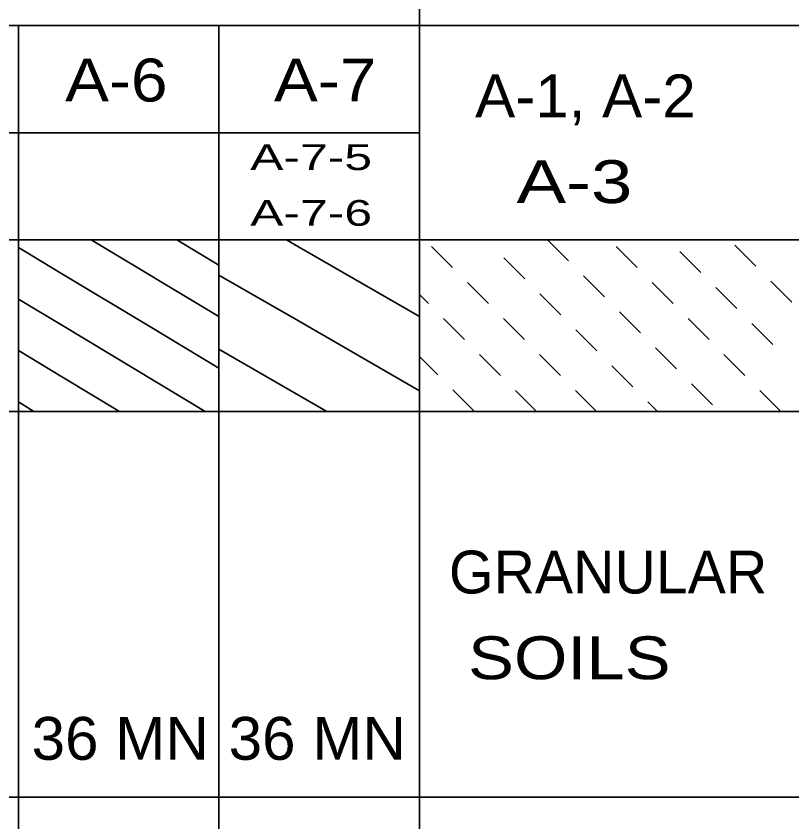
# Model space of a CAD drawing. Extents: x 2137492.6 to 2137529.1, y 2137475.8 to 2137563.
# Drawn here: x 2137498.33 to 2137500.14, y 2137553.765 to 2137555.645 of the extents above; entities that cross this region are included whole.
import ezdxf
from ezdxf.enums import TextEntityAlignment as Align

# ---------------------------------------------------------------- set-up
doc = ezdxf.new("R2010")
doc.units = 0
doc.header["$LTSCALE"] = 0.04
doc.layers.add('1', color=7, linetype='Continuous', lineweight=35)

msp = doc.modelspace()

# ---------------------------------------------------------------- linework, layer by layer
at = {"layer": '1'}
for p, q in [((2137499.271, 2137556.123), (2137499.271, 2137551.631)), ((2137499.271, 2137556.123), (2137499.271, 2137555.098)), ((2137493.171, 2137555.623), (2137501.871, 2137555.623)), ((2137498.335, 2137554.186), (2137498.335, 2137555.623)), ((2137498.803, 2137552.923), (2137498.803, 2137555.623)), ((2137494.121, 2137555.373), (2137499.271, 2137555.373)), ((2137493.171, 2137555.123), (2137501.871, 2137555.123)), ((2137498.505, 2137555.123), (2137498.803, 2137554.944)), ((2137498.705, 2137555.123), (2137498.803, 2137555.064)), ((2137498.989, 2137555.107), (2137498.961, 2137555.123)), ((2137499.57, 2137555.123), (2137499.619, 2137555.074)), ((2137500.056, 2137555.062), (2137500.007, 2137555.111)), ((2137498.335, 2137555.105), (2137498.438, 2137555.043)), ((2137499.271, 2137554.944), (2137498.989, 2137555.107)), ((2137499.271, 2137553.823), (2137499.271, 2137555.093)), ((2137499.348, 2137555.059), (2137499.299, 2137555.108)), ((2137499.779, 2137555.059), (2137499.73, 2137555.108)), ((2137499.879, 2137555.096), (2137499.928, 2137555.047)), ((2137499.517, 2137555.032), (2137499.468, 2137555.081)), ((2137498.438, 2137555.043), (2137498.638, 2137554.923)), ((2137498.989, 2137554.934), (2137498.803, 2137555.041)), ((2137499.654, 2137555.039), (2137499.703, 2137554.99)), ((2137499.432, 2137554.975), (2137499.383, 2137555.024)), ((2137499.863, 2137554.975), (2137499.814, 2137555.024)), ((2137500.14, 2137554.978), (2137500.091, 2137555.027)), ((2137499.601, 2137554.948), (2137499.552, 2137554.997)), ((2137499.963, 2137555.012), (2137500.012, 2137554.963)), ((2137498.335, 2137554.985), (2137498.438, 2137554.923)), ((2137499.292, 2137554.975), (2137499.271, 2137554.996)), ((2137499.738, 2137554.955), (2137499.787, 2137554.906)), ((2137498.438, 2137554.923), (2137498.771, 2137554.723)), ((2137498.638, 2137554.923), (2137498.803, 2137554.824)), ((2137499.271, 2137554.771), (2137498.989, 2137554.934)), ((2137499.376, 2137554.891), (2137499.327, 2137554.94)), ((2137499.516, 2137554.891), (2137499.467, 2137554.94)), ((2137499.947, 2137554.891), (2137499.898, 2137554.94)), ((2137500.047, 2137554.928), (2137500.096, 2137554.879)), ((2137499.636, 2137554.913), (2137499.685, 2137554.864)), ((2137498.335, 2137554.865), (2137498.438, 2137554.803)), ((2137498.989, 2137554.761), (2137498.803, 2137554.868)), ((2137499.822, 2137554.871), (2137499.871, 2137554.822)), ((2137499.314, 2137554.808), (2137499.271, 2137554.851)), ((2137499.46, 2137554.807), (2137499.411, 2137554.856)), ((2137499.6, 2137554.807), (2137499.551, 2137554.856)), ((2137500.031, 2137554.807), (2137499.982, 2137554.856)), ((2137499.72, 2137554.829), (2137499.769, 2137554.78)), ((2137498.438, 2137554.803), (2137498.571, 2137554.723)), ((2137499.398, 2137554.724), (2137499.349, 2137554.773)), ((2137499.544, 2137554.723), (2137499.495, 2137554.772)), ((2137499.684, 2137554.723), (2137499.635, 2137554.772)), ((2137499.906, 2137554.787), (2137499.955, 2137554.738)), ((2137500.115, 2137554.723), (2137500.066, 2137554.772)), ((2137499.055, 2137554.723), (2137498.989, 2137554.761)), ((2137498.335, 2137554.745), (2137498.371, 2137554.723)), ((2137499.804, 2137554.745), (2137499.827, 2137554.723)), ((2137493.171, 2137554.723), (2137501.871, 2137554.723)), ((2137498.335, 2137552.223), (2137498.335, 2137554.226)), ((2137493.171, 2137553.823), (2137501.871, 2137553.823))]:
    msp.add_line(p, q, dxfattribs=at)

# ---------------------------------------------------------------- texts
for s, width, p in [('A-6', 1.15, (2137498.5635, 2137555.446)), ('A-7', 1.15, (2137499.051, 2137555.446)), ('36 MN', 1.05, (2137498.5725, 2137553.91)), ('36 MN', 1.05, (2137499.0325, 2137553.91))]:
    msp.add_text(s, height=0.1, dxfattribs=dict(at, width=width)).set_placement(p, align=Align.CENTER)
for s, height, width, p in [('A-1, A-2', 0.1, 1.05, (2137499.401, 2137555.409)), ('A-7-5', 0.06, 1.45, (2137498.876, 2137555.286)), ('  A-3', 0.1, 1.3, (2137499.401, 2137555.209)), ('A-7-6', 0.06, 1.45, (2137498.876, 2137555.156)), (' SOILS', 0.1, 1.2, (2137499.34, 2137554.098))]:
    msp.add_text(s, height=height, dxfattribs=dict(at, width=width)).set_placement(p)
msp.add_text('GRANULAR', height=0.1, dxfattribs=at).set_placement((2137499.34, 2137554.298))

doc.saveas('drawing.dxf')
